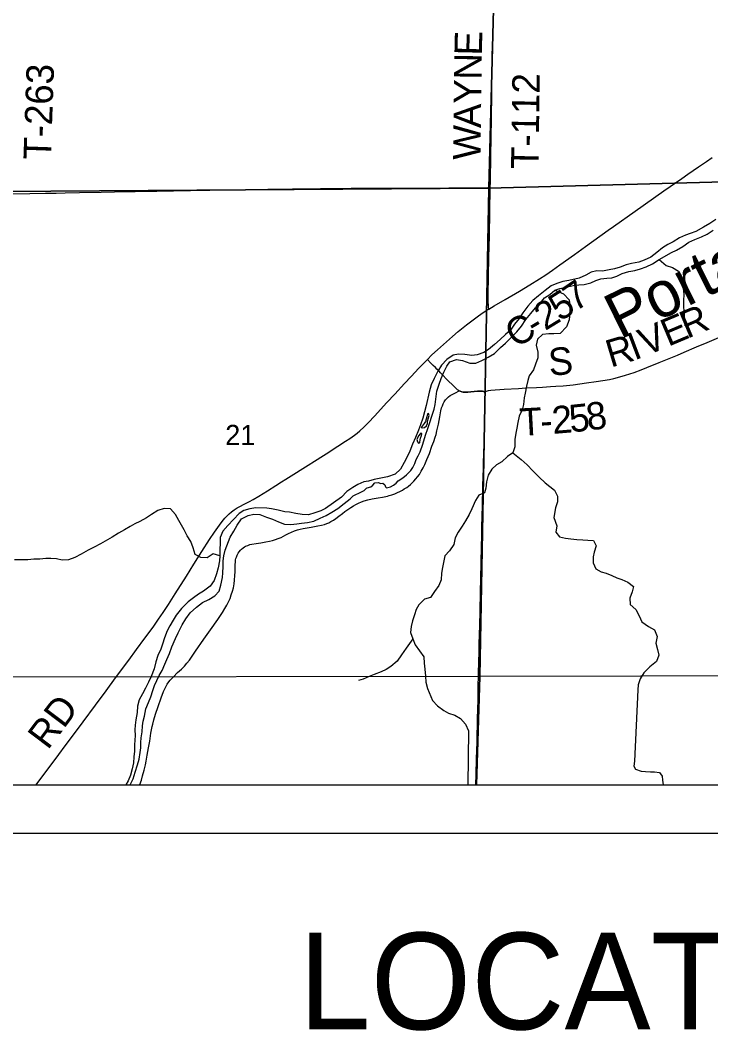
# Model space of a CAD drawing. Extents: x -8.3 to 42.1, y 0 to 22.
# Drawn here: x 3.85 to 5.28, y 13.591 to 15.682 of the extents above; entities that cross this region are included whole.
import ezdxf

# ---------------------------------------------------------------- set-up
doc = ezdxf.new("R2010")
doc.units = 0
for name, color, linetype in [('Default', 7, 'Continuous'), ('GM_X_County_Road', 7, 'Continuous'), ('GM_X_County_Road_Text', 7, 'Continuous'), ('GM_X_Major_River', 7, 'Continuous'), ('GM_X_Major_River_Text', 7, 'Continuous'), ('GM_X_Minor_River', 7, 'Continuous'), ('GM_X_Section', 7, 'Continuous'), ('GM_X_Section_Text', 7, 'Continuous'), ('GM_X_Township_Road', 7, 'Continuous'), ('GM_X_Township_Road_Text', 7, 'Continuous'), ('SH_Cut_Line', 7, 'Continuous'), ('SH_Data', 7, 'Continuous'), ('SH_Text', 7, 'Continuous')]:
    doc.layers.add(name, color=color, linetype=linetype)

msp = doc.modelspace()

# ---------------------------------------------------------------- linework, layer by layer
at = {"layer": 'Default'}
for points in [[(3.7889, 14.1), (4.7944, 14.1), (4.8014, 14.3239), (3.7926, 14.3222)], [(4.7944, 14.1), (5.7957, 14.1), (5.8007, 14.322), (5.8007, 14.3261), (4.8014, 14.3239)]]:
    msp.add_lwpolyline(points, close=True, dxfattribs=at)
at = {"layer": 'GM_X_County_Road'}
for points in [[(4.8199, 15.0841), (4.8311, 15.0909), (4.8541, 15.104), (4.8837, 15.1211), (4.905, 15.134), (4.9249, 15.1463), (4.9379, 15.1548), (4.952, 15.1645), (4.9671, 15.1754), (4.9975, 15.197), (5.0203, 15.2132), (5.067, 15.2469), (5.0783, 15.2551), (5.1227, 15.2866), (5.1826, 15.3284), (5.2195, 15.3543), (5.2322, 15.3633), (5.254, 15.3781), (5.2707, 15.3896), (5.2822, 15.3976)], [(4.693, 14.9794), (4.7024, 14.989), (4.7138, 14.9995), (4.7452, 15.0273), (4.7569, 15.0375), (4.7737, 15.0513), (4.7847, 15.0599), (4.7959, 15.0682), (4.8061, 15.0753), (4.8179, 15.0829), (4.8199, 15.0841)], [(3.8833, 14.1), (3.895, 14.1153), (3.9184, 14.1466), (3.9303, 14.1626), (3.9436, 14.1806), (3.9604, 14.203), (3.9808, 14.2304), (4.0059, 14.2644), (4.0278, 14.2939), (4.0477, 14.3209), (4.0751, 14.3579), (4.091, 14.3794), (4.1082, 14.403), (4.1251, 14.426), (4.1365, 14.4423), (4.1464, 14.4566), (4.1571, 14.4727), (4.1711, 14.4947), (4.1941, 14.5316), (4.2097, 14.5563), (4.2261, 14.5828), (4.242, 14.6073), (4.2524, 14.6228), (4.2625, 14.637), (4.268, 14.6446), (4.2736, 14.6513), (4.2779, 14.6559), (4.2824, 14.6602), (4.2877, 14.6647), (4.2932, 14.6688), (4.299, 14.6726), (4.3045, 14.6756), (4.3138, 14.6802), (4.3245, 14.6857), (4.3321, 14.6898), (4.3439, 14.6966), (4.3619, 14.7078), (4.3792, 14.7187), (4.3913, 14.7264), (4.4002, 14.732), (4.4518, 14.7644), (4.4539, 14.7658), (4.4833, 14.7845), (4.5079, 14.8002), (4.5235, 14.8104), (4.5324, 14.8162), (4.542, 14.823), (4.5473, 14.8272), (4.553, 14.8319), (4.5612, 14.8395), (4.571, 14.849), (4.5838, 14.8625), (4.6093, 14.8906), (4.6254, 14.9079), (4.6457, 14.9298), (4.6593, 14.9443), (4.6754, 14.9616), (4.685, 14.9714), (4.693, 14.9794)], [(4.759, 14.915), (4.7583, 14.9153), (4.7556, 14.917), (4.752, 14.9201), (4.7442, 14.9277), (4.7376, 14.9343), (4.7204, 14.952), (4.7171, 14.9553), (4.7128, 14.9596), (4.7095, 14.9629), (4.7051, 14.9672), (4.6997, 14.9727), (4.693, 14.9794)], [(4.8114, 14.912), (4.8097, 14.9135), (4.8072, 14.914), (4.8058, 14.9142), (4.8028, 14.9143), (4.7968, 14.9139), (4.7829, 14.9125), (4.7767, 14.9121), (4.7704, 14.9121), (4.7672, 14.9123), (4.7641, 14.9128), (4.7611, 14.9139), (4.759, 14.915)], [(4.793, 14.1), (4.7936, 14.1218), (4.7938, 14.1281), (4.7944, 14.1467), (4.7947, 14.156), (4.7951, 14.1684), (4.7957, 14.1902), (4.7962, 14.2104), (4.7964, 14.2166), (4.7969, 14.2368), (4.7977, 14.2756), (4.7982, 14.2974), (4.799, 14.3316), (4.8001, 14.3751), (4.8004, 14.3891), (4.8009, 14.4124), (4.8013, 14.4279), (4.8019, 14.4606), (4.8028, 14.4979), (4.804, 14.5585), (4.8049, 14.5942), (4.8054, 14.6129), (4.8056, 14.6206), (4.8058, 14.6315), (4.8059, 14.6377), (4.8063, 14.6517), (4.807, 14.6812), (4.8076, 14.7123), (4.8077, 14.7185), (4.8082, 14.7371), (4.8088, 14.7542), (4.8092, 14.7651), (4.8096, 14.7853), (4.8102, 14.8055), (4.8106, 14.8226), (4.8109, 14.8365), (4.8111, 14.8459), (4.8113, 14.8552), (4.8118, 14.8709), (4.8123, 14.8885), (4.8123, 14.8952), (4.8123, 14.9072), (4.8122, 14.9098), (4.8114, 14.912)]]:
    msp.add_lwpolyline(points, dxfattribs=at)
at = {"layer": 'GM_X_Major_River'}
for p, q in [((4.6934, 14.8472), (4.6935, 14.851)), ((4.6746, 14.8219), (4.6718, 14.8155))]:
    msp.add_line(p, q, dxfattribs=at)
for points in [[(5.2901, 15.2696), (5.2774, 15.2612), (5.2647, 15.2535), (5.2486, 15.2448), (5.2367, 15.2402), (5.2272, 15.237), (5.2149, 15.2316), (5.2018, 15.2232), (5.1904, 15.2178), (5.1799, 15.2104), (5.1676, 15.2009), (5.1552, 15.1917), (5.1418, 15.1852), (5.1304, 15.1813), (5.1152, 15.1786), (5.1041, 15.1758), (5.0922, 15.1708), (5.0804, 15.1673), (5.0694, 15.1649), (5.0557, 15.1626), (5.0436, 15.1629), (5.0318, 15.1605), (5.021, 15.1539), (5.0069, 15.1482), (4.9855, 15.1434), (4.9734, 15.141), (4.9608, 15.1368), (4.9493, 15.1321), (4.9365, 15.1226), (4.923, 15.1115), (4.9114, 15.1016), (4.9005, 15.0901), (4.8903, 15.0763), (4.8832, 15.0647), (4.8735, 15.0528), (4.8648, 15.0401), (4.8548, 15.0312), (4.8439, 15.0208), (4.8319, 15.0109), (4.8195, 15.0002), (4.8095, 14.994), (4.7961, 14.989), (4.7848, 14.9881), (4.7704, 14.99), (4.7572, 14.9907), (4.7461, 14.9883), (4.7331, 14.9795), (4.7222, 14.968), (4.7143, 14.9553), (4.7071, 14.9403), (4.7011, 14.9275), (4.6969, 14.9121), (4.6901, 14.8844), (4.687, 14.8715), (4.6835, 14.8585), (4.6786, 14.8442), (4.6745, 14.8337), (4.6681, 14.8186), (4.6621, 14.8047), (4.6564, 14.7901), (4.6516, 14.7799), (4.6452, 14.7668), (4.6373, 14.753), (4.6261, 14.7426), (4.6104, 14.7369), (4.5967, 14.7342), (4.583, 14.7311), (4.5708, 14.728), (4.5613, 14.7263), (4.5487, 14.7209), (4.5383, 14.7151), (4.526, 14.7063), (4.5154, 14.6948), (4.4823, 14.6712)], [(4.6833, 14.8046), (4.689, 14.8231), (4.6939, 14.8366), (4.698, 14.8494), (4.7021, 14.8626), (4.7067, 14.8769), (4.7088, 14.8867), (4.7125, 14.914), (4.717, 14.9286), (4.7215, 14.9407), (4.7267, 14.9538), (4.7331, 14.9658), (4.7394, 14.9748), (4.7535, 14.9798), (4.7659, 14.9776), (4.7806, 14.9723), (4.7931, 14.972), (4.8053, 14.9777), (4.8184, 14.9846), (4.8318, 14.9919), (4.8446, 15.0045), (4.8547, 15.0134), (4.8671, 15.026), (4.878, 15.0367), (4.8878, 15.0486), (4.8968, 15.0624), (4.907, 15.0747), (4.9165, 15.0866), (4.9264, 15.0963), (4.9354, 15.107), (4.9462, 15.1144), (4.9566, 15.1229), (4.9669, 15.1268), (4.9799, 15.1291), (4.9944, 15.1326), (5.0061, 15.1338), (5.0171, 15.1351), (5.0309, 15.1385), (5.0419, 15.1428), (5.0519, 15.1464), (5.0644, 15.1476), (5.0747, 15.1488), (5.085, 15.152), (5.0961, 15.1574), (5.1098, 15.1617), (5.1224, 15.1636), (5.1338, 15.1672), (5.146, 15.1714), (5.1591, 15.1775), (5.1729, 15.1867), (5.1983, 15.2013), (5.2082, 15.206), (5.2213, 15.2136), (5.234, 15.2224), (5.2463, 15.2278), (5.26, 15.2335), (5.2719, 15.239), (5.2842, 15.247)], [(4.6935, 14.851), (4.6948, 14.8571), (4.6965, 14.8639), (4.6951, 14.8681), (4.6932, 14.867), (4.6919, 14.8613), (4.6906, 14.8564), (4.689, 14.8515), (4.6862, 14.847), (4.6803, 14.8388), (4.6837, 14.838), (4.6871, 14.8387), (4.6914, 14.8427), (4.6934, 14.8472)], [(4.6718, 14.8155), (4.671, 14.814), (4.6724, 14.8094), (4.6746, 14.8067), (4.6765, 14.8074), (4.6773, 14.8078), (4.6782, 14.8134), (4.679, 14.8172), (4.6807, 14.8221), (4.6812, 14.8259), (4.6797, 14.8278), (4.6785, 14.8263), (4.6746, 14.8219)], [(4.5074, 14.6716), (4.5208, 14.6821), (4.5328, 14.6917), (4.5394, 14.6973), (4.5566, 14.7056), (4.5624, 14.7085), (4.567, 14.7137), (4.5682, 14.7144), (4.5758, 14.7165), (4.5801, 14.7194), (4.5843, 14.7243), (4.5912, 14.7252), (4.5964, 14.7228), (4.601, 14.7235), (4.6051, 14.7203), (4.6065, 14.7165), (4.6083, 14.7142), (4.6167, 14.7163), (4.6228, 14.7195), (4.6283, 14.7239), (4.6325, 14.7284), (4.6418, 14.735), (4.6499, 14.7413), (4.6584, 14.7498), (4.6628, 14.7565), (4.6668, 14.7648), (4.6696, 14.7727), (4.674, 14.7805), (4.678, 14.7888), (4.6833, 14.8046)], [(4.4823, 14.6712), (4.4727, 14.6668), (4.4601, 14.6624), (4.4468, 14.6585), (4.4338, 14.6587), (4.4206, 14.6608), (4.4073, 14.6636), (4.3979, 14.6645), (4.3842, 14.6678), (4.3702, 14.6707), (4.3604, 14.6723), (4.338, 14.6727), (4.3258, 14.671), (4.3132, 14.6674), (4.3032, 14.6611), (4.2916, 14.6484), (4.2801, 14.636), (4.2697, 14.6246), (4.2642, 14.6111), (4.2639, 14.5994), (4.2637, 14.5865), (4.2637, 14.5738), (4.263, 14.563), (4.2601, 14.549), (4.2565, 14.5361), (4.2517, 14.5225), (4.2435, 14.5105), (4.2297, 14.5004), (4.219, 14.4942), (4.209, 14.4867), (4.1975, 14.4782), (4.1843, 14.4647), (4.1727, 14.4508), (4.1669, 14.4407), (4.1598, 14.429), (4.1547, 14.4184), (4.1489, 14.404), (4.1444, 14.3905), (4.1412, 14.3803), (4.1353, 14.3675), (4.131, 14.3543), (4.1273, 14.3399), (4.1214, 14.324), (4.1155, 14.312), (4.1092, 14.2999), (4.103, 14.2879), (4.0967, 14.2754), (4.0931, 14.2623), (4.0921, 14.2497), (4.0892, 14.2341), (4.0882, 14.2231), (4.0877, 14.2133), (4.0883, 14.2015), (4.0874, 14.192), (4.0869, 14.1822), (4.0871, 14.1696), (4.0857, 14.1579), (4.0848, 14.1453), (4.0819, 14.1329), (4.0783, 14.1196), (4.0736, 14.1079), (4.0689, 14.1)], [(4.078, 14.1), (4.0839, 14.1123), (4.0883, 14.1259), (4.0927, 14.141), (4.0967, 14.1531), (4.0988, 14.1668), (4.0997, 14.1763), (4.0999, 14.1873), (4.1004, 14.1968), (4.1025, 14.2096), (4.1035, 14.2221), (4.1044, 14.2316), (4.1072, 14.2418), (4.1105, 14.257), (4.1156, 14.2698), (4.1203, 14.2815), (4.1247, 14.2951), (4.1279, 14.3049), (4.133, 14.3159), (4.1381, 14.326), (4.144, 14.3362), (4.1495, 14.3494), (4.1538, 14.3592), (4.1593, 14.3717), (4.1641, 14.3853), (4.1718, 14.4024), (4.1771, 14.4139), (4.1853, 14.4305), (4.1931, 14.4429), (4.202, 14.4553), (4.2151, 14.4673), (4.2278, 14.4769), (4.2408, 14.4832), (4.2529, 14.4908), (4.2618, 14.5006), (4.2656, 14.5128), (4.2689, 14.5287), (4.2698, 14.5386), (4.2704, 14.5517), (4.2706, 14.5632), (4.2715, 14.5735), (4.2743, 14.5852), (4.2849, 14.612), (4.2924, 14.6248), (4.2991, 14.6372), (4.3084, 14.65), (4.3218, 14.6566), (4.3336, 14.6595), (4.3465, 14.6589), (4.3597, 14.6534)], [(4.3597, 14.6534), (4.3726, 14.6494), (4.385, 14.6435), (4.3975, 14.6391), (4.4103, 14.6384), (4.4229, 14.6399), (4.4324, 14.6408), (4.445, 14.6425), (4.458, 14.6454), (4.471, 14.6513), (4.4832, 14.6568), (4.4955, 14.6638), (4.5074, 14.6716)]]:
    msp.add_lwpolyline(points, dxfattribs=at)
at = {"layer": 'GM_X_Minor_River'}
msp.add_line((4.7778, 14.2117), (4.7766, 14.1), dxfattribs=at)
for points in [[(5.1729, 15.1867), (5.187, 15.1738), (5.2002, 15.1701), (5.2128, 15.1626), (5.2171, 15.153), (5.221, 15.1396), (5.2226, 15.127), (5.2238, 15.1149), (5.2231, 15.1009), (5.2231, 15.0876), (5.2243, 15.0743), (5.2247, 15.0617), (5.2259, 15.0492)], [(4.9566, 15.1229), (4.975, 15.1156), (4.9864, 15.1032), (4.9876, 15.0898), (4.988, 15.0766), (4.9862, 15.0614), (4.9809, 15.0475), (4.9677, 15.0338), (4.9544, 15.0326), (4.9445, 15.0328), (4.9313, 15.0312), (4.9208, 15.0216), (4.9182, 15.0092), (4.9213, 14.9951), (4.9214, 14.9833), (4.9165, 14.9697), (4.9124, 14.9585), (4.9038, 14.9458), (4.9009, 14.936), (4.8979, 14.9243), (4.8953, 14.9099), (4.8935, 14.9001), (4.8917, 14.8865), (4.8891, 14.8755), (4.8828, 14.8624), (4.8802, 14.8496), (4.8784, 14.8378), (4.8758, 14.8276), (4.874, 14.8144), (4.8736, 14.7992), (4.8695, 14.7868), (4.8587, 14.7791), (4.8467, 14.768), (4.8363, 14.7618), (4.8266, 14.7525), (4.8184, 14.7402), (4.8154, 14.7263), (4.8136, 14.7138), (4.8114, 14.7036), (4.7992, 14.6989), (4.7928, 14.6877), (4.7846, 14.6708)], [(4.8695, 14.7868), (4.8872, 14.7725), (4.8996, 14.7618), (4.9114, 14.749), (4.9243, 14.7361), (4.9365, 14.7245), (4.9462, 14.7166), (4.9558, 14.7092), (4.9619, 14.6972), (4.9621, 14.6851), (4.9584, 14.6731)], [(4.2637, 14.5738), (4.2499, 14.5777), (4.2372, 14.5697), (4.2239, 14.5701), (4.2123, 14.5762), (4.2085, 14.5899), (4.2036, 14.603), (4.1955, 14.615), (4.1898, 14.6273), (4.1782, 14.6467), (4.1714, 14.659), (4.1614, 14.6707), (4.1482, 14.6715), (4.1351, 14.6673), (4.122, 14.6593), (4.1115, 14.6524), (4.098, 14.6448), (4.0872, 14.6394), (4.0775, 14.634), (4.0663, 14.6275), (4.0536, 14.6203), (4.0408, 14.6119), (4.0261, 14.6036), (4.0165, 14.5982), (4.003, 14.5914), (3.9906, 14.5853), (3.9767, 14.5769), (3.9632, 14.5701), (3.9502, 14.5652), (3.9372, 14.5644), (3.9251, 14.567), (3.9134, 14.5678), (3.9031, 14.5677), (3.8905, 14.5665), (3.8784, 14.5665), (3.8658, 14.5653), (3.8529, 14.5649), (3.8381, 14.565)], [(4.7846, 14.6708), (4.7793, 14.6592), (4.7721, 14.6461), (4.7646, 14.6349), (4.7566, 14.6226), (4.7506, 14.611), (4.7479, 14.5967), (4.7388, 14.584), (4.7293, 14.5733), (4.7263, 14.5597), (4.7241, 14.5495), (4.7222, 14.5374), (4.7215, 14.5237), (4.7166, 14.5121), (4.7075, 14.4998), (4.6995, 14.4871), (4.6869, 14.4841), (4.6751, 14.4723), (4.6699, 14.4622), (4.6662, 14.4516), (4.6624, 14.4388), (4.6594, 14.4271), (4.6583, 14.415), (4.6625, 14.4016), (4.6674, 14.3893), (4.6769, 14.3769), (4.6853, 14.3645), (4.6861, 14.3511), (4.688, 14.3389), (4.6887, 14.3248), (4.6895, 14.3119), (4.6929, 14.2993), (4.7036, 14.2739), (4.7136, 14.263), (4.727, 14.2534), (4.7367, 14.2478), (4.7499, 14.2437), (4.7614, 14.2369), (4.7718, 14.2255), (4.7778, 14.2117)], [(4.9584, 14.6731), (4.9548, 14.653), (4.961, 14.6357), (4.9591, 14.6228), (4.9661, 14.6127), (4.9789, 14.6097), (4.9895, 14.6086), (5.0024, 14.6071), (5.0149, 14.6064), (5.0248, 14.6061), (5.0369, 14.605), (5.0423, 14.5942), (5.0381, 14.5814), (5.0359, 14.5716), (5.0363, 14.559), (5.0413, 14.5467), (5.0529, 14.5407), (5.0627, 14.5374), (5.0747, 14.5328), (5.0848, 14.528), (5.0954, 14.5243), (5.1081, 14.5193), (5.1193, 14.5099), (5.1167, 14.4989), (5.1121, 14.4858), (5.1125, 14.4725), (5.1244, 14.4626), (5.1312, 14.4495), (5.1369, 14.4368), (5.1507, 14.4273), (5.1627, 14.4201), (5.1687, 14.4066), (5.1657, 14.393), (5.1691, 14.38), (5.1718, 14.3678), (5.1672, 14.355), (5.1536, 14.3436), (5.1411, 14.3314), (5.1335, 14.3191), (5.129, 14.3063), (5.1283, 14.2961)], [(4.6625, 14.4016), (4.649, 14.3826), (4.6391, 14.3688), (4.6304, 14.3558), (4.6175, 14.3444), (4.6074, 14.3382), (4.597, 14.3332), (4.5828, 14.3279), (4.5724, 14.324), (4.5601, 14.3183), (4.5505, 14.3156)], [(5.1283, 14.2961), (5.1214, 14.1489), (5.12, 14.1383), (5.124, 14.1321), (5.1356, 14.128), (5.1447, 14.1273), (5.155, 14.1266), (5.1633, 14.1268), (5.1732, 14.1253), (5.1786, 14.118), (5.1795, 14.1096), (5.1806, 14.1)]]:
    msp.add_lwpolyline(points, dxfattribs=at)
at = {"layer": 'GM_X_Section'}
for points in [[(3.8435, 16.3264), (4.8464, 16.3395), (4.8204, 15.3344), (3.8127, 15.327)], [(4.8464, 16.3395), (5.8503, 16.3424), (5.8197, 15.3608), (4.8204, 15.3344)], [(5.8197, 15.3608), (5.8007, 14.3261), (4.8014, 14.3239), (4.8204, 15.3344)], [(4.8204, 15.3344), (4.8014, 14.3239), (3.7926, 14.3222), (3.8127, 15.327)]]:
    msp.add_lwpolyline(points, close=True, dxfattribs=at)
at = {"layer": 'GM_X_Township_Road'}
for points in [[(4.8231, 15.3353), (4.8234, 15.3475), (4.8243, 15.4034), (4.8248, 15.4361), (4.826, 15.5263), (4.8273, 15.6102), (4.8281, 15.6429), (4.8305, 15.73), (4.8318, 15.7797), (4.8336, 15.8605), (4.8358, 15.9631), (4.8376, 16.0611), (4.8383, 16.0969), (4.8391, 16.1435), (4.8402, 16.1979), (4.8407, 16.2197), (4.8412, 16.2414), (4.8416, 16.2663), (4.8421, 16.2865), (4.8424, 16.3083), (4.8431, 16.3301), (4.8432, 16.3332), (4.8434, 16.3396)], [(3.8122, 15.3224), (3.8281, 15.3223), (3.87, 15.3229), (3.9027, 15.3236), (3.9245, 15.3239), (3.9432, 15.3242), (3.9726, 15.3249), (4.0177, 15.3258), (4.0456, 15.3264), (4.0878, 15.327), (4.1328, 15.3276), (4.2026, 15.3295), (4.3223, 15.3316), (4.3628, 15.3322), (4.4141, 15.3328), (4.4716, 15.3335), (4.5354, 15.3338), (4.5913, 15.3342), (4.6939, 15.3344), (4.7375, 15.3347), (4.7795, 15.3351), (4.8183, 15.3353), (4.8231, 15.3353)], [(4.8199, 15.0841), (4.8194, 15.0885), (4.8191, 15.0918), (4.8188, 15.0987), (4.8189, 15.1142), (4.8203, 15.1904), (4.8213, 15.2355), (4.8231, 15.3353)], [(4.8114, 14.912), (4.815, 14.9145), (4.8193, 14.9156), (4.824, 14.9162), (4.8518, 14.9181), (4.8813, 14.9199), (4.8968, 14.9209), (4.9185, 14.922), (4.9309, 14.9227), (4.948, 14.9235), (4.9588, 14.9242), (4.9743, 14.9255), (4.9944, 14.9276), (5.0222, 14.9311), (5.0422, 14.9339), (5.0561, 14.9361), (5.0698, 14.9386), (5.079, 14.9407), (5.091, 14.9438), (5.103, 14.9473), (5.1207, 14.9531), (5.1354, 14.9584), (5.147, 14.9628), (5.173, 14.9733), (5.2103, 14.9889), (5.2245, 14.995), (5.2502, 15.006), (5.2717, 15.0149), (5.3191, 15.0347)], [(4.098, 14.1), (4.0981, 14.1005), (4.1011, 14.1094), (4.1036, 14.1184), (4.1067, 14.1304), (4.1092, 14.141), (4.1109, 14.1486), (4.1133, 14.1608), (4.116, 14.1762), (4.1183, 14.19), (4.1209, 14.2068), (4.1235, 14.2205), (4.1245, 14.2251), (4.1268, 14.2341), (4.1303, 14.2459), (4.1356, 14.2621), (4.1418, 14.2797), (4.1468, 14.2927), (4.1486, 14.297), (4.1513, 14.3025), (4.1544, 14.3078), (4.1579, 14.3128), (4.1608, 14.3164), (4.1672, 14.3231), (4.176, 14.3318), (4.1841, 14.3389), (4.1901, 14.3455), (4.1951, 14.3512), (4.2003, 14.3577), (4.2132, 14.3761), (4.2304, 14.4009), (4.2442, 14.4207), (4.259, 14.4416), (4.2687, 14.4564), (4.2738, 14.4645), (4.2778, 14.4714), (4.2811, 14.4783), (4.2845, 14.4854), (4.2871, 14.4926), (4.2894, 14.5002), (4.2917, 14.5076), (4.2929, 14.5153), (4.294, 14.523), (4.2947, 14.5326), (4.2952, 14.5403), (4.2952, 14.5435), (4.2953, 14.5559), (4.2955, 14.5605), (4.2961, 14.565), (4.2967, 14.568), (4.2976, 14.5709), (4.2993, 14.5751), (4.3014, 14.5791), (4.3031, 14.5816), (4.306, 14.5851), (4.3081, 14.5873), (4.3116, 14.5902), (4.3142, 14.5919), (4.3168, 14.5934), (4.321, 14.5952), (4.3253, 14.5968), (4.3298, 14.5979), (4.3387, 14.5992), (4.348, 14.6005), (4.3587, 14.6022), (4.3664, 14.6038), (4.3726, 14.6053), (4.3784, 14.6071), (4.3843, 14.6094), (4.3901, 14.6117), (4.3999, 14.6167), (4.4055, 14.6198), (4.4114, 14.6226), (4.4179, 14.6251), (4.424, 14.6272), (4.4299, 14.629), (4.4358, 14.6302), (4.4525, 14.6331), (4.4664, 14.6353), (4.474, 14.6368), (4.4801, 14.6385), (4.4845, 14.6402), (4.4888, 14.642), (4.493, 14.6442), (4.4985, 14.6473), (4.5037, 14.6507), (4.51, 14.6553), (4.5173, 14.6611), (4.522, 14.6649), (4.5282, 14.6694), (4.5345, 14.6738), (4.5398, 14.677), (4.5451, 14.68), (4.5507, 14.6827), (4.5564, 14.685), (4.5622, 14.687), (4.5696, 14.6891), (4.5787, 14.6911), (4.5909, 14.6933), (4.6, 14.695), (4.6107, 14.6972), (4.6137, 14.698), (4.6197, 14.6997), (4.6256, 14.7019), (4.6299, 14.7037), (4.637, 14.7072), (4.6411, 14.7094), (4.6451, 14.7119), (4.6504, 14.7151), (4.6541, 14.7179), (4.6577, 14.7212), (4.6613, 14.7245), (4.6651, 14.7283), (4.6693, 14.7327), (4.6725, 14.7369), (4.6763, 14.742), (4.6803, 14.7487), (4.6841, 14.7556), (4.6876, 14.7625), (4.6921, 14.7725), (4.697, 14.7852), (4.7022, 14.8002), (4.7062, 14.8102), (4.709, 14.819), (4.711, 14.8248), (4.7128, 14.8323), (4.7159, 14.846), (4.7188, 14.8613), (4.7211, 14.8734), (4.7225, 14.8794), (4.724, 14.8838), (4.7257, 14.888), (4.7278, 14.8921), (4.7303, 14.8959), (4.7322, 14.8982), (4.7343, 14.9004), (4.7366, 14.9024), (4.7403, 14.905), (4.7443, 14.9074), (4.7511, 14.9109), (4.759, 14.915)], [(4.759, 14.915), (4.7611, 14.9139), (4.7641, 14.9128), (4.7672, 14.9123), (4.7704, 14.9121), (4.7767, 14.9121), (4.7829, 14.9125), (4.7968, 14.9139), (4.8028, 14.9143), (4.8058, 14.9142), (4.8072, 14.914), (4.8097, 14.9135), (4.8114, 14.912)], [(2.1, 14.1), (7.8013, 14.1)]]:
    msp.add_lwpolyline(points, dxfattribs=at)
at = {"layer": 'SH_Cut_Line'}
msp.add_lwpolyline([(2.1, 14.1), (7.8013, 14.1)], dxfattribs=at)
at = {"layer": 'SH_Data'}
for p, q in [((2.1, 14.1), (8.9, 14.1)), ((2, 14), (9, 14))]:
    msp.add_line(p, q, dxfattribs=at)

# ---------------------------------------------------------------- texts
at = {"layer": 'GM_X_County_Road_Text'}
for s, height, rotation, p in [('7', 0.0568, 34.4263, (4.9987, 15.0772)), ('5', 0.0568, 32.5265, (4.9675, 15.0573)), ('2', 0.0568, 31.3922, (4.9366, 15.0384)), ('C', 0.0568, 30.5059, (4.8755, 15.0023)), ('-', 0.0568, 30.7328, (4.9159, 15.0261)), ('RD', 0.05682, 53.0322, (3.9073, 14.1704))]:
    msp.add_text(s, height=height, rotation=rotation, dxfattribs=at).set_placement(p)
at = {"layer": 'GM_X_Major_River_Text'}
msp.add_text('Portage', height=0.09475, rotation=26.2292, dxfattribs=at).set_placement((5.0913, 15.0198))
at = {"layer": 'GM_X_Section_Text'}
msp.add_text('21', height=0.04186, rotation=0, dxfattribs=at).set_placement((4.2746, 14.8026))
at = {"layer": 'GM_X_Township_Road_Text'}
for s, height, rotation, p in [('E', 0.0568, 88.6628, (4.8056, 15.6081)), ('N', 0.0568, 89.2168, (4.8049, 15.5583)), ('T-263', 0.05682, 88.0353, (3.9136, 15.392)), ('Y', 0.0568, 89.2313, (4.8042, 15.5083)), ('T-112', 0.05682, 89.175, (4.9228, 15.3732)), ('A', 0.0568, 89.235, (4.8036, 15.4583)), ('W', 0.0568, 89.2336, (4.8027, 15.3925)), ('E', 0.0568, 22.825, (5.1913, 15.0057)), ('R', 0.0568, 22.8238, (5.2305, 15.0222)), ('V', 0.0568, 22.4398, (5.1448, 14.9864)), ('I', 0.0568, 20.6972, (5.1212, 14.9775)), ('R', 0.0568, 16.6413, (5.0724, 14.9627)), ('S', 0.0568, 4.9763, (4.9458, 14.9458)), ('5', 0.0568, 6.0926, (4.9892, 14.8286)), ('8', 0.0568, 7.3117, (5.0253, 14.8325)), ('T', 0.0568, 3.1344, (4.8854, 14.8216)), ('2', 0.0568, 4.7423, (4.9529, 14.8256)), ('-', 0.0568, 3.5978, (4.9283, 14.824))]:
    msp.add_text(s, height=height, rotation=rotation, dxfattribs=at).set_placement(p)
at = {"layer": 'SH_Text'}
msp.add_text('LOCATION MAP', height=0.2, dxfattribs=at).set_placement((4.4269, 13.5938))

doc.saveas('drawing.dxf')
